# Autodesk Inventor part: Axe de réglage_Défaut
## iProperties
Shininess: 64.0
Length Units: 11269
Angle Units: 11279
Time Units: 11290
Mass Units: 11283
Length Display Precision: 3
Angle Display Precision: 2
Compacted: True
Part Number: Axe de réglage_Défaut
Document SubType Name: Modeling
Created: 2006-01
Material: Par défaut
Designer: riri
Density: 0.0
Volumn: 0.0
Area: 0.0
PropertySet Name: Model Information
Control State: 0
Master: False
Checked Out: False
Author: riri
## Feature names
1. Base1
